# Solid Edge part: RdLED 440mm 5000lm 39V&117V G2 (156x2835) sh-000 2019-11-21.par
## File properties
Author: sylwester.cabaj
Template: iso metric part.par
Last saved by: sylwester.cabaj
Revision: 3
Application: Solid Edge
Gęstość: 0,000 kg/m^3
Dokładność: 0,990
Username: sylwester.cabaj
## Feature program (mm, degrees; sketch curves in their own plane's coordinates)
body "unnamed Body 1"
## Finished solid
Body 1: solid body, 3325 faces, 8656 edges, 5642 vertices.
  Faces by surface: plane 2820, cylinder 237, spline 160, cone 52, torus 22, sphere 20, spun 14
  Edges by curve: line 7560, curve on surface 564, circle 312, ellipse 132, spline 76, intersection 12
Bounding box of the edges (mm; curved faces can reach further): 428.000 x 4.450 x 428.000, from (-214, -3.45, -214) to (214, 1, 214).
Cylindrical faces by radius (mm): R0.2 x78, R0.2002 x4, R0.2169 x6, R0.25 x24, R0.3 x4, R0.3373 x6, R0.4 x16, R0.4006 x4, R0.4008 x4, R0.525 x4, R0.6 x24, R1 x14, R1.0894 x4, R1.1 x28, R2.25 x12, R5 x1, R219.9999 x4
Conical faces (half-angle, radius in mm at the cone's reference point): 0.5 deg R0.5056 x8, 0.5 deg R1.0082 x8, 1 deg R0.5511 x4, 10 deg R0.2132 x4, 10 deg R0.4132 x4, 18.4844 deg R1.0657 x8, 27.363 deg R0.6214 x4, 45 deg R0.575 x4, 45 deg R0.625 x8
Toroidal faces (ring radius, tube radius in mm): R0.1 r0.2 x2, R0.8 r0.2 x8, R0.8522 r0.3 x4, R0.9002 r0.2 x2, R0.9018 r0.2 x2, R1.3 r0.2 x4
Spherical faces by radius (mm): R0.2 x16, R0.6 x4
Planar faces by outward normal: +x 47, +y 15, +z 46, -x 47, -y 507, -z 46, oblique 2112
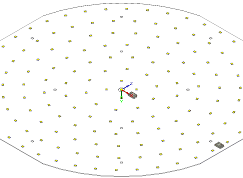
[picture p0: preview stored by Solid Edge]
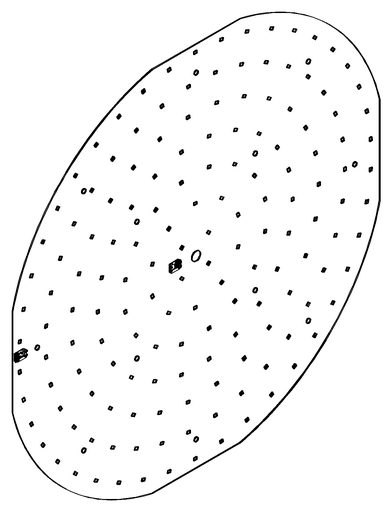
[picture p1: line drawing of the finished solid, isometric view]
